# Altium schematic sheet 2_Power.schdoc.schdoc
size 309 x 223 mm; Symbol: Sheet-Symbol_A4; Device: Sheet-Symbol_A4; Company: EasyEDA.com; Drawed: EasyEDA Pro; Reviewed: EasyEDA Pro; Version: V2.3; Page Size: A4; @Project Name: RecoveryBoard_W24Edits; @Page Count: 3; @Update Date: 2024-02-20; @Create Date: 2024-01-31; @Schematic Name: Schematic; Part Number: JLCPCB-002; @Page No: 3; @Page Name: Power
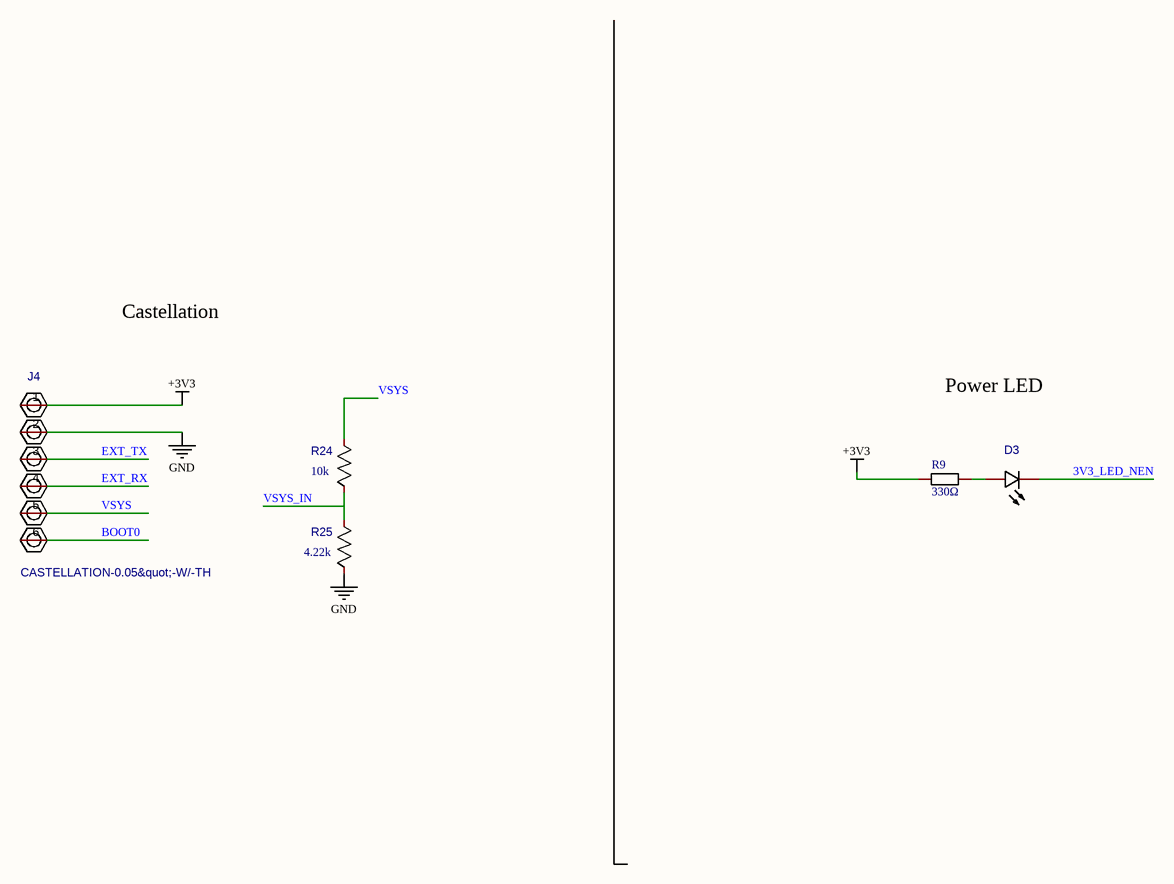
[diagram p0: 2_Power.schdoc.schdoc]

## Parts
D3  16-213/SDRC/S530-A3/TR8  [LED0402-RD]  (value not drawn)
J4  CASTELLATION-0.05&quot;-W/-TH  [CASTELLATION-0.05"-W/-TH]
R9  330Ω  [R0603]
R24  10k  [R0402]
R25  4.22k  [R0402]

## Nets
+3V3: J4.1 R9.1
GND: J4.2 R25.1
3V3_LED_NEN: D3.1(-)
BOOT0: J4.6
EXT_RX: J4.4
EXT_TX: J4.3
VSYS: J4.5 R24.2
VSYS_IN: R24.1 R25.2
NetD3_2: D3.2(+) R9.2

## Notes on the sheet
- Castellation
- Power LED

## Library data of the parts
D3 = 16-213SDRC/S530-A3/TR8: Manufacturer: EVERLIGHT(亿光); Convert to PCB: yes
J4 = CASTELLATION-0.05"-W/-TH: Convert to PCB: yes
R9 = RC0603JR-07330RL: Manufacturer: YAGEO(国巨); Add into BOM: yes; Tolerance: ±5%; Temperature Coefficient: ±100ppm/℃; Description: Type:Thick Film Resistors Resistance: Tolerance:±5% Tolerance:±5% Power(Watts): Overload Voltage (Max): Temperature Coefficient:±100ppm/℃ Temperature Coefficient:±100ppm/℃ Operating Temperature Range:-55℃~+155℃ Operating Temperature Range:-55℃~+155℃
R24 = RC0603FR-0710RL: Manufacturer Part: TR0402D10KQ1025; Symbol: 10; Convert to PCB: yes; Origin Footprint: R0603
R25 = RC0603FR-0710RL: Manufacturer Part: RT0402BRD074K22L; Symbol: 10; Convert to PCB: yes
